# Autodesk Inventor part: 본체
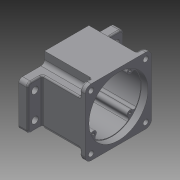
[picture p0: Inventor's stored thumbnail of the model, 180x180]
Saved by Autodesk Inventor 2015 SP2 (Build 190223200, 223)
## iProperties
Created: 2015-06
Part Number: 본체
Material: 일반
Document SubType Name: Modeling
Designer: AMC
Density: 1 g/cm^3
Appearance: 기본값
Author: AMC
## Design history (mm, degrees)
sketch "스케치1"
  geometry: L1 (0, 0)-(90, 0); L2 (90, 0)-(90, 90); L3 (90, 90)-(0, 90); L4 (0, 90)-(0, 0)
  constraints: 8 end point, 2 parallel, 1 horizontal, 1 perpendicular
  dimensions: "d0" = 90 distance of L3.end L2.end; "d1" = 90 distance of L2.end L1.end
extrude "돌출1" new body sketch "스케치1" distance "d2" = 58; taper "d3" = 0 deg
sketch "스케치2"
  geometry: L1 (0, 0)-(-90, 0) reference; L2 (-90, 0)-(-90, 90) reference; L3 (-90, 90)-(0, 90) reference; L4 (0, 90)-(0, 0) reference; L5 (20, 75)-(20, 15); L6 (-110, 15)-(-110, 75); L7 (-90, 90)-(0, 90) reference; L8 (0, 0)-(-90, 0) reference; L9 (-75, 90)-(-15, 90); L10 (-15, 0)-(-75, 0); L11 (-110, 75)-(-75, 75); L12 (-15, 75)-(20, 75); L13 (20, 15)-(-15, 15); L14 (-75, 15)-(-110, 15); L15 (-75, 0)-(-75, 15); L16 (-75, 75)-(-75, 90); L17 (-15, 90)-(-15, 75); L18 (-15, 15)-(-15, 0); 10 further points
  constraints: 24 end point, 10 parallel, 8 midpoint, 4 perpendicular, 3 horizontal, 2 horizontal alignment, 2 point on line, 2 vertical alignment, 1 coincident
  dimensions: "d4" = 130 distance of L5.end L6.start; "d5" = 60 distance of L5.start L5.end; "d6" = 60 distance of L10.start L10.end; "d7" = 35 distance between parallel lines of L6 L16; "d8" = 60 distance of L6.start L6.end; "d9" = 90 distance of L10.start L9.end; "d10" = 35 distance between parallel lines of L5 L18
extrude "돌출2" join sketch "스케치2" distance "d11" = 12; taper "d12" = 0 deg
fillet "모깎기1" dims "d13" = 8
fillet "모깎기2" dims "d14" = 5
sketch "스케치3"
  geometry: L1 (-75, 80)-(-75, 90) reference; L2 (-75, 90)-(-82, 90) reference; L3 (-90, 82)-(-90, 75) reference; L4 (-90, 75)-(-80, 75) reference; L5 (-80, 15)-(-90, 15) reference; L6 (-90, 15)-(-90, 8) reference; L7 (-82, 0)-(-75, 0) reference; L8 (-75, 0)-(-75, 10) reference; L9 (-15, 10)-(-15, 0) reference; L10 (-15, 0)-(-8, 0) reference; L11 (0, 8)-(0, 15) reference; L12 (0, 15)-(-10, 15) reference; L13 (-10, 75)-(0, 75) reference; L14 (0, 75)-(0, 82) reference; L15 (-8, 90)-(-15, 90) reference; L16 (-15, 90)-(-15, 80) reference; A1 r 5 centre (-80, 80) between (-80, 75) and (-75, 80) reference; A2 r 8 centre (-82, 82) between (-82, 90) and (-90, 82) reference; A3 r 5 centre (-80, 10) between (-75, 10) and (-80, 15) reference; A4 r 8 centre (-82, 8) between (-90, 8) and (-82, 0) reference; A5 r 5 centre (-10, 10) between (-10, 15) and (-15, 10) reference; A6 r 8 centre (-8, 8) between (-8, 0) and (0, 8) reference; A7 r 5 centre (-10, 80) between (-15, 80) and (-10, 75) reference; A8 r 8 centre (-8, 82) between (0, 82) and (-8, 90) reference; 1 further point
extrude "돌출3" cut sketch "스케치3" distance "d15" = 51; taper "d16" = 0 deg
sketch "스케치4"
  geometry: L1 (75, 90)-(75, 80) reference; L2 (80, 75)-(110, 75) reference; L3 (110, 75)-(110, 15) reference; L4 (110, 15)-(80, 15) reference; L5 (75, 10)-(75, 0) reference; L6 (75, 0)-(15, 0) reference; L7 (15, 0)-(15, 10) reference; L8 (10, 15)-(-20, 15) reference; L9 (-20, 15)-(-20, 75) reference; L10 (-20, 75)-(10, 75) reference; L11 (15, 80)-(15, 90) reference; L12 (15, 90)-(75, 90) reference; L13 (0, 15)-(0, 75) reference; A1 r 5 centre (80, 80) between (75, 80) and (80, 75) reference; A2 r 5 centre (80, 10) between (80, 15) and (75, 10) reference; A3 r 5 centre (10, 10) between (15, 10) and (10, 15) reference; A4 r 5 centre (10, 80) between (10, 75) and (15, 80) reference; 4 further points
  constraints: 2 midpoint, 1 horizontal alignment, 1 vertical alignment
hole "구멍1" sketch "스케치4" at (45, 45) diameter "d17" = 78; stored, may be unused: countersink angle "d21" = 90 deg, drill point angle "d23" = 0 deg; dims "d18" = 6, "d19" = 80, "d20" = 9, "d22" = 61
fillet "모깎기3" dims "d24" = 5
sketch "스케치5"
  geometry: L1 (-82, 90)-(-8, 90) reference; L2 (-45, 90)-(-45, 0); L3 (-110, 70)-(-110, 20) reference; L4 (-90, 75)-(-105, 75) reference; C1 r 4.5 at (-100, 62.5); C2 r 4.5 at (-100, 27.5); C3 r 4.5 at (10, 62.5); C4 r 4.5 at (10, 27.5); 1 further point
  constraints: 4 centre point, 2 end point, 2 symmetric about line, 1 midpoint, 1 vertical, 2 other
  dimensions: "d25" = 9 diameter of C1; "d26" = 9 diameter of C2; "d27" = 35 distance of C2.centre C1.centre; "d29" = 10 distance from line of C1.centre L3; "d30" = 10 distance from line of L3 C2.centre; "d31" = 12.5 distance from line of C1.centre L4
extrude "돌출4" cut sketch "스케치5" stored distance "d33" = 51; taper "d34" = 0 deg
sketch "스케치6"
  geometry: L1 (-75, 90)-(-75, 80) reference; L2 (-82, 90)-(-75, 90) reference; L3 (-90, 75)-(-90, 82) reference; L4 (-80, 75)-(-90, 75) reference; L5 (0, 75)-(-10, 75) reference; L6 (0, 82)-(0, 75) reference; L7 (-15, 90)-(-8, 90) reference; L8 (-15, 80)-(-15, 90) reference; L9 (-15, 0)-(-15, 10) reference; L10 (-8, 0)-(-15, 0) reference; L11 (0, 15)-(0, 8) reference; L12 (-10, 15)-(0, 15) reference; L13 (-90, 15)-(-80, 15) reference; L14 (-90, 8)-(-90, 15) reference; L15 (-75, 0)-(-82, 0) reference; L16 (-75, 10)-(-75, 0) reference; C1 r 3.5 at (-82, 82); C2 r 3.5 at (-8, 82); C3 r 3.5 at (-8, 8); C4 r 3.5 at (-82, 8); A1 r 5 centre (-80, 80) between (-80, 75) and (-75, 80) reference; A2 r 8 centre (-82, 82) between (-82, 90) and (-90, 82) reference; A3 r 5 centre (-10, 80) between (-15, 80) and (-10, 75) reference; A4 r 8 centre (-8, 82) between (0, 82) and (-8, 90) reference; A5 r 5 centre (-10, 10) between (-10, 15) and (-15, 10) reference; A6 r 8 centre (-8, 8) between (-8, 0) and (0, 8) reference; A7 r 5 centre (-80, 10) between (-75, 10) and (-80, 15) reference; A8 r 8 centre (-82, 8) between (-90, 8) and (-82, 0) reference; 1 further point
  constraints: 4 centre point, 4 coincident
  dimensions: "d35" = 7 diameter of C1; "d36" = 7 diameter of C2; "d37" = 7 diameter of C3; "d38" = 7 diameter of C4
extrude "돌출5" cut sketch "스케치6" stored distance "d39" = 51; taper "d40" = 0 deg
sketch "스케치7"
  geometry: L1 (0, 0)-(0, 66.237); L2 (0, 0)-(-52.363, 52.363); L3 (-21.763, 27.411)-(-25.096, 31.148); L4 (-27.411, 21.763)-(-31.148, 25.096); C1 r 39 at (0, 0) reference; A1 r 40 centre (0, 0) between (-31.148, 25.096) and (-25.096, 31.148) reference; A2 r 35 centre (0, 0) between (-24.749, 24.749) and (-21.763, 27.411); A3 r 4 centre (-24.749, 24.749) between (-27.411, 21.763) and (-21.763, 27.411); 1 further point
  constraints: 8 end point, 7 point on circle, 2 centre point, 2 coincident, 2 tangent, 1 point on line, 1 vertical
  dimensions: "d41" = 70 diameter of A2; "d42" = 45 deg angle of L1 L2; "d43" = 8 diameter of A3
extrude "돌출6" join sketch "스케치7" stored distance "d44" = 51; taper "d45" = 0 deg
fillet "모깎기4" dims "d49" = 3.5
fillet "모깎기5" dims "d50" = 2
sketch "스케치8"
  geometry: L1 (-27.507, 21.849)-(-27.411, 21.763) reference; L2 (-21.763, 27.411)-(-21.849, 27.507) reference; L3 (21.849, 27.507)-(21.763, 27.411) reference; L4 (27.411, 21.763)-(27.507, 21.849) reference; L5 (27.507, -21.849)-(27.411, -21.763) reference; L6 (21.763, -27.411)-(21.849, -27.507) reference; L7 (-21.849, -27.507)-(-21.763, -27.411) reference; L8 (-27.411, -21.763)-(-27.507, -21.849) reference; C1 r 40 at (0, 0) reference; A1 r 3.5 centre (-29.836, 19.237) between (-27.507, 21.849) and (-32.778, 21.133) reference; A2 r 4 centre (-24.749, 24.749) between (-27.411, 21.763) and (-21.763, 27.411) reference; A3 r 3.5 centre (-19.237, 29.836) between (-21.133, 32.778) and (-21.849, 27.507) reference; A4 r 39 centre (0, 0) between (21.133, 32.778) and (-21.133, 32.778) reference; A5 r 3.5 centre (19.237, 29.836) between (21.849, 27.507) and (21.133, 32.778) reference; A6 r 4 centre (24.749, 24.749) between (21.763, 27.411) and (27.411, 21.763) reference; A7 r 3.5 centre (29.836, 19.237) between (32.778, 21.133) and (27.507, 21.849) reference; A8 r 39 centre (0, 0) between (32.778, -21.133) and (32.778, 21.133) reference; A9 r 3.5 centre (29.836, -19.237) between (27.507, -21.849) and (32.778, -21.133) reference; A10 r 4 centre (24.749, -24.749) between (27.411, -21.763) and (21.763, -27.411) reference; A11 r 3.5 centre (19.237, -29.836) between (21.133, -32.778) and (21.849, -27.507) reference; A12 r 39 centre (0, 0) between (-21.133, -32.778) and (21.133, -32.778) reference; A13 r 3.5 centre (-19.237, -29.836) between (-21.849, -27.507) and (-21.133, -32.778) reference; A14 r 4 centre (-24.749, -24.749) between (-21.763, -27.411) and (-27.411, -21.763) reference; A15 r 3.5 centre (-29.836, -19.237) between (-32.778, -21.133) and (-27.507, -21.849) reference; A16 r 39 centre (0, 0) between (-32.778, 21.133) and (-32.778, -21.133) reference; 1 further point
hole "구멍2" sketch "스케치8" at (24.749, -24.749), (24.749, 24.749), (-24.749, 24.749), (-24.749, -24.749) diameter "d51" = 3.242; stored, may be unused: countersink angle "d55" = 90 deg, drill point angle "d57" = 118 deg; dims "d52" = 12, "d53" = 80, "d54" = 9, "d56" = 15
sketch "스케치9"
  geometry: L1 (20.271, -28.742)-(20.356, -28.838) reference; L2 (28.838, -20.356)-(28.742, -20.271) reference; L3 (28.742, 20.271)-(28.838, 20.356) reference; L4 (20.356, 28.838)-(20.271, 28.742) reference; L5 (-20.271, 28.742)-(-20.356, 28.838) reference; L6 (-28.838, 20.356)-(-28.742, 20.271) reference; L7 (-28.742, -20.271)-(-28.838, -20.356) reference; L8 (-20.356, -28.838)-(-20.271, -28.742) reference; A1 r 20.5 centre (0, 11) between (7.402, -8.117) and (-7.402, -8.117); A2 r 37 centre (0, 0) between (-20.049, -31.097) and (20.049, -31.097) reference; A3 r 6 centre (24.749, -24.749) between (28.742, -20.271) and (20.271, -28.742) reference; A4 r 37 centre (0, 0) between (31.097, -20.049) and (31.097, 20.049) reference; A5 r 6 centre (24.749, 24.749) between (20.271, 28.742) and (28.742, 20.271) reference; A6 r 37 centre (0, 0) between (20.049, 31.097) and (-20.049, 31.097) reference; A7 r 6 centre (-24.749, 24.749) between (-28.742, 20.271) and (-20.271, 28.742) reference; A8 r 37 centre (0, 0) between (-31.097, 20.049) and (-31.097, -20.049) reference; A9 r 6 centre (-24.749, -24.749) between (-20.271, -28.742) and (-28.742, -20.271) reference; A10 r 14 centre (0, -20) between (-7.402, -8.117) and (7.402, -8.117); A11 r 1.5 centre (19.237, -29.836) between (20.049, -31.097) and (20.356, -28.838) reference; A12 r 1.5 centre (29.836, -19.237) between (28.838, -20.356) and (31.097, -20.049) reference; A13 r 1.5 centre (29.836, 19.237) between (31.097, 20.049) and (28.838, 20.356) reference; A14 r 1.5 centre (19.237, 29.836) between (20.356, 28.838) and (20.049, 31.097) reference; A15 r 1.5 centre (-19.237, 29.836) between (-20.049, 31.097) and (-20.356, 28.838) reference; A16 r 1.5 centre (-29.836, 19.237) between (-28.838, 20.356) and (-31.097, 20.049) reference; A17 r 1.5 centre (-29.836, -19.237) between (-31.097, -20.049) and (-28.838, -20.356) reference; A18 r 1.5 centre (-19.237, -29.836) between (-20.356, -28.838) and (-20.049, -31.097) reference; 1 further point
  constraints: 4 point on circle, 2 centre point, 2 vertical alignment
  dimensions: "d58" = 41 diameter of A1; "d59" = 28 diameter of A10; "d60" = 11 distance of A2.centre A1.centre; "d61" = 20 distance of A2.centre A10.centre
extrude "돌출7" join sketch "스케치9" distance "d62" = 7; taper "d63" = 0 deg
sketch "스케치10"
  geometry: C1 r 25 at (-45, 56); A1 r 20.5 centre (-45, 56) between (-37.598, 36.883) and (-52.402, 36.883) reference; 1 further point
  constraints: 1 centre point, 1 coincident
  dimensions: "d64" = 50 diameter of C1
extrude "돌출8" join sketch "스케치10" distance "d65" = 7; taper "d66" = 0 deg
sketch "스케치11"
  geometry: C1 r 25 at (0, 0) reference; 1 further point
hole "구멍3" sketch "스케치11" at (0, 0) diameter "d67" = 25; stored, may be unused: countersink angle "d71" = 90 deg, drill point angle "d73" = 0 deg; dims "d68" = 12, "d69" = 32, "d70" = 8, "d72" = 13
sketch "스케치12"
  geometry: C1 r 12.5 at (0, 11) reference; A1 r 14 centre (0, -20) between (-7.402, -8.117) and (7.402, -8.117) reference; A2 r 20.5 centre (0, 11) between (7.402, -8.117) and (-7.402, -8.117) reference; 1 further point
hole "구멍4" sketch "스케치12" at (0, -20) diameter "d74" = 19; stored, may be unused: countersink angle "d78" = 90 deg, drill point angle "d80" = 0 deg; dims "d75" = 12, "d76" = 22, "d77" = 7, "d79" = 8
sketch "스케치13"
  geometry: C1 r 11 at (0, -20) reference; C2 r 12.5 at (0, 11) reference; C3 r 17.5 at (0, 11); A1 r 14 centre (0, -20) between (-7.402, -8.117) and (7.402, -8.117) reference; A2 r 20.5 centre (0, 11) between (7.402, -8.117) and (-7.402, -8.117) reference; 1 further point
  constraints: 1 centre point, 1 coincident
  dimensions: "d81" = 35 diameter of C3
extrude "돌출9" cut sketch "스케치13" distance "d82" = 10; taper "d83" = 0 deg
chamfer "모따기1" distance "d84" = 1; stored, may be unused: second distance "d85" = 2, angle "d86" = 45 deg
fillet "모깎기6" dims "d87" = 0.3
fillet "모깎기7" dims "d88" = 2
fillet "모깎기8" dims "d89" = 3
fillet "모깎기9" dims "d90" = 2
fillet "모깎기10" dims "d91" = 2
fillet "모깎기11" dims "d92" = 2
sketch "스케치14"
  geometry: L1 (-75, 0)-(-15, 0) reference; 3 further points
  constraints: 1 midpoint, 1 vertical alignment, 1 other
  dimensions: "d93" = 15 distance from line of L1 point (-45, 15)
feature "엠보싱1" sketch "스케치14" dims "d0" = 90, "d1" = 90, "d4" = 130, "d5" = 60, "d6" = 60, "d7" = 35, "d8" = 60, "d9" = 90, "d10" = 35, "d94" = 0.5, "d95" = 0
fillet "모깎기12" dims "d96" = 2
fillet "모깎기13" dims "d97" = 2
node "솔리드1"
pattern_circular "원형 패턴1" dims angle "d47" = 360 deg
node "투영된 루프1"
node "투영된 루프2"
node "투영된 루프3"
node "투영된 루프4"
node "투영된 루프5"
node "투영된 루프6"
node "투영된 루프7"
node "투영된 루프8"
node "투영된 루프9"
node "투영된 루프10"
node "투영된 루프11"
node "투영된 루프12"
node "투영된 루프13"
node "투영된 루프14"
node "투영된 루프15"
